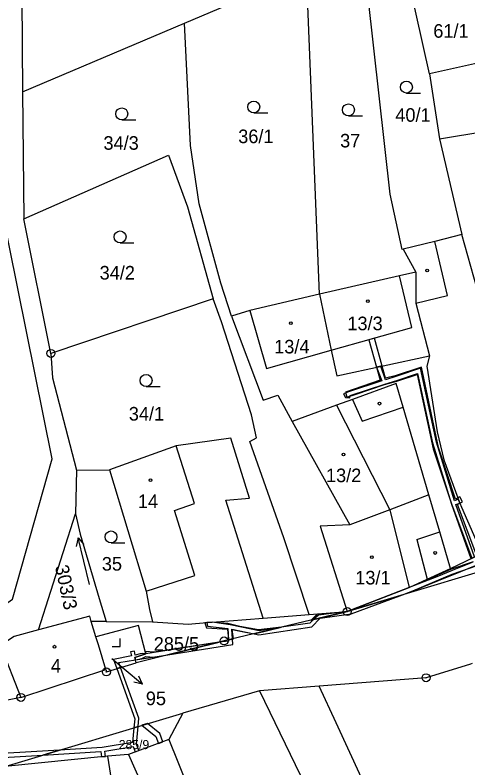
# Model space of a CAD drawing. Extents: x -779723 to -777378, y -1011169 to -1009297.
# Drawn here: x -779128.1 to -779071.4, y -1010301.7 to -1010207.4 of the extents above; entities that cross this region are included whole.
import ezdxf

# ---------------------------------------------------------------- set-up
doc = ezdxf.new("R2010")
doc.units = 0
for name, color, linetype in [('Hranice parcel', 7, 'Continuous'), ('Parcelní čísla', 7, 'Continuous'), ('Pop  PČ popisy', 7, 'Continuous'), ('Vnitřní kresba', 7, 'Continuous'), ('Věcná břemena k části', 7, 'Continuous'), ('Značky bodu BP', 7, 'Continuous'), ('Značky budov', 7, 'Continuous'), ('Značky kultur', 7, 'Continuous')]:
    doc.layers.add(name, color=color, linetype=linetype)

msp = doc.modelspace()

# ---------------------------------------------------------------- linework, layer by layer
at = {"layer": 'Hranice parcel'}
for p, q in [((-779127.44, -1010190.39), (-779127.2, -1010217)), ((-779081.11, -1010229.82), (-779084.45, -1010200.01)), ((-779106.91, -1010208.39), (-779091.64, -1010201.91)), ((-779089.99, -1010242.37), (-779091.64, -1010201.91)), ((-779127.2, -1010217), (-779106.91, -1010208.39)), ((-779106.16, -1010223.74), (-779106.91, -1010208.39)), ((-779127.2, -1010217), (-779127.06, -1010232.92)), ((-779079.62, -1010236.77), (-779081.11, -1010229.82)), ((-779123.64, -1010249.79), (-779127.06, -1010232.92)), ((-779068.8, -1010246.85), (-779072.13, -1010234.9)), ((-779079.48, -1010236.74), (-779079.62, -1010236.77)), ((-779079.48, -1010236.74), (-779077.92, -1010239.59)), ((-779103.32, -1010242.93), (-779123.64, -1010249.79)), ((-779076.18, -1010250.09), (-779076.54, -1010251.4)), ((-779095.21, -1010255.03), (-779093.41, -1010258.3)), ((-779093.41, -1010258.3), (-779086.17, -1010271.27)), ((-779107.93, -1010261.36), (-779116.32, -1010264.37)), ((-779120.42, -1010264.41), (-779120.56, -1010269.87)), ((-779120.42, -1010264.41), (-779116.32, -1010264.37)), ((-779116.32, -1010264.37), (-779111.69, -1010279.58)), ((-779125.19, -1010284.44), (-779120.56, -1010269.87)), ((-779073.55, -1010276.72), (-779069.64, -1010274.85)), ((-779117.61, -1010280.51), (-779116.7, -1010283.39)), ((-779097.04, -1010282.96), (-779091.27, -1010282.5)), ((-779091.27, -1010282.5), (-779086.5, -1010282.14)), ((-779118.01, -1010285.29), (-779118.58, -1010283.38)), ((-779116.7, -1010283.39), (-779118.58, -1010283.38)), ((-779116.7, -1010283.39), (-779110.91, -1010283.41)), ((-779110.91, -1010283.41), (-779106.44, -1010283.7)), ((-779129.95, -1010286.4), (-779127.4, -1010292.89)), ((-779127.4, -1010292.89), (-779116.78, -1010289.39)), ((-779127.4, -1010292.89), (-779137.19, -1010294.93)), ((-779129.38, -1010301.54), (-779107.13, -1010294.85))]:
    msp.add_line(p, q, dxfattribs=at)
for points in [[(-779076.2, -1010214.76), (-779078.76, -1010203.29), (-779079.59, -1010199.58)], [(-779063.08, -1010211.82), (-779064.77, -1010212.2), (-779069.82, -1010213.33), (-779076.2, -1010214.76)], [(-779076.2, -1010214.76), (-779074.94, -1010222.88), (-779072.13, -1010234.9)], [(-779139.88, -1010286.86), (-779135.87, -1010285.81), (-779128.47, -1010280.58), (-779123.49, -1010263.01), (-779132.14, -1010220.3)], [(-779101.02, -1010245.11), (-779102.33, -1010241), (-779105.07, -1010231.05), (-779106.16, -1010223.74)], [(-779127.06, -1010232.92), (-779108.9, -1010224.93), (-779106.53, -1010231.41), (-779103.32, -1010242.93)], [(-779072.13, -1010234.9), (-779075.52, -1010235.75), (-779079.48, -1010236.74)], [(-779077.92, -1010239.59), (-779079.97, -1010240.06), (-779089.99, -1010242.37)], [(-779077.92, -1010239.59), (-779077.92, -1010243.48), (-779076.18, -1010250.09)], [(-779089.99, -1010242.37), (-779098.71, -1010244.39), (-779101.02, -1010245.11)], [(-779089.99, -1010242.37), (-779088.5, -1010249.4), (-779087.83, -1010252.59), (-779076.18, -1010250.09)], [(-779091.27, -1010282.5), (-779094.46, -1010272.88), (-779098.72, -1010260.84), (-779097.87, -1010260.36), (-779098.52, -1010257.5), (-779102.28, -1010245.85), (-779103.32, -1010242.93)], [(-779101.02, -1010245.11), (-779097.05, -1010255.65), (-779095.21, -1010255.03)], [(-779123.64, -1010249.79), (-779123.44, -1010252.85), (-779120.42, -1010264.41)], [(-779037.66, -1010249.73), (-779040.66, -1010261.41), (-779050.79, -1010270.34), (-779061.75, -1010274.71), (-779086.5, -1010282.14)], [(-779076.54, -1010251.4), (-779075.23, -1010259.6), (-779074.39, -1010263.13), (-779072.64, -1010267.9), (-779072.39, -1010268.55), (-779072.2, -1010269.07), (-779069.64, -1010274.85)], [(-779076.26, -1010267.51), (-779079.49, -1010256.51), (-779080.36, -1010253.56), (-779085.85, -1010255.56), (-779087.87, -1010256.29), (-779093.41, -1010258.3)], [(-779097.04, -1010282.96), (-779101.73, -1010268.16), (-779098.76, -1010267.92), (-779101.09, -1010260.41), (-779107.93, -1010261.36)], [(-779076.26, -1010267.51), (-779081.16, -1010269.37), (-779086.17, -1010271.27)], [(-779073.55, -1010276.72), (-779074.9, -1010272.13), (-779076.26, -1010267.51)], [(-779120.56, -1010269.87), (-779119.96, -1010272.44), (-779117.61, -1010280.51)], [(-779086.17, -1010271.27), (-779089.91, -1010271.43), (-779086.5, -1010282.14)], [(-779086.5, -1010282.14), (-779078.75, -1010279.13), (-779076.48, -1010278.07), (-779073.55, -1010276.72)], [(-779111.69, -1010279.58), (-779111.28, -1010281.87), (-779110.91, -1010283.41)], [(-779118.58, -1010283.38), (-779118.78, -1010282.71), (-779125.19, -1010284.44)], [(-779086.5, -1010282.14), (-779101.94, -1010285.82), (-779112.94, -1010288.54)], [(-779106.44, -1010283.7), (-779104.11, -1010283.52), (-779103.42, -1010283.46), (-779097.04, -1010282.96)], [(-779112.94, -1010288.54), (-779113.12, -1010287.88), (-779111.73, -1010287.42), (-779112.67, -1010283.87), (-779118.01, -1010285.29)], [(-779125.19, -1010284.44), (-779128.24, -1010285.26), (-779129.95, -1010286.4)], [(-779116.78, -1010289.39), (-779117.7, -1010286.32), (-779118.01, -1010285.29)], [(-779116.78, -1010289.39), (-779116.69, -1010289.7), (-779112.94, -1010288.54)], [(-779070.83, -1010288.65), (-779071.05, -1010288.72), (-779076.63, -1010290.43), (-779079.33, -1010290.64), (-779090.04, -1010291.48)], [(-779107.24, -1010315.22), (-779102.83, -1010313.22), (-779096.1, -1010312.69), (-779092.74, -1010318.04), (-779088.64, -1010315.52), (-779088.67, -1010313.8), (-779087.34, -1010313.07), (-779081.53, -1010309.87), (-779087.9, -1010296.09), (-779090.04, -1010291.48)], [(-779090.04, -1010291.48), (-779097.5, -1010292.06), (-779107.13, -1010294.85)], [(-779107.13, -1010294.85), (-779108.85, -1010298.16), (-779113.91, -1010300.03)], [(-779113.91, -1010300.03), (-779116.55, -1010300.26), (-779129.38, -1010301.54)], [(-779113.91, -1010300.03), (-779109.3, -1010310.52), (-779107.24, -1010315.22)]]:
    msp.add_lwpolyline(points, dxfattribs=at)
at = {"layer": 'Pop  PČ popisy'}
for p, q in [((-779116, -1010288.01), (-779114.46, -1010289.32)), ((-779114.46, -1010289.32), (-779112.161, -1010291.249)), ((-779112.161, -1010291.249), (-779112.606, -1010290.222)), ((-779112.161, -1010291.249), (-779113.25, -1010290.989))]:
    msp.add_line(p, q, dxfattribs=at)
at = {"layer": 'Vnitřní kresba'}
for p, q in [((-779074.94, -1010222.88), (-779067.91, -1010221.73)), ((-779078.41, -1010246.55), (-779079.97, -1010240.06)), ((-779098.71, -1010244.39), (-779096.62, -1010251.69)), ((-779088.5, -1010249.4), (-779078.41, -1010246.55)), ((-779096.62, -1010251.69), (-779088.5, -1010249.4)), ((-779085.85, -1010255.56), (-779084.65, -1010258.28)), ((-779087.87, -1010256.29), (-779081.16, -1010269.37)), ((-779084.65, -1010258.28), (-779079.49, -1010256.51)), ((-779105.66, -1010268.59), (-779107.93, -1010261.36)), ((-779108.14, -1010269.47), (-779105.66, -1010268.59)), ((-779105.62, -1010277.63), (-779108.14, -1010269.47)), ((-779081.16, -1010269.37), (-779078.75, -1010279.13)), ((-779077.79, -1010273.1), (-779074.9, -1010272.13)), ((-779077.79, -1010273.1), (-779076.48, -1010278.07)), ((-779111.69, -1010279.58), (-779105.62, -1010277.63)), ((-779097.5, -1010292.06), (-779087.34, -1010313.07)), ((-779108.85, -1010298.16), (-779102.83, -1010313.22)), ((-779116.55, -1010300.26), (-779115.17, -1010309.24))]:
    msp.add_line(p, q, dxfattribs=at)
msp.add_lwpolyline([(-779077.92, -1010243.48), (-779073.96, -1010242.51), (-779075.52, -1010235.75)], dxfattribs=at)
at = {"layer": 'Věcná břemena k části'}
for points in [[(-779082.13, -1010251.37), (-779083.1, -1010247.88), (-779083.78, -1010248.07), (-779082.82, -1010251.51)], [(-779086.16, -1010255.06), (-779081.79, -1010253.63), (-779080.27, -1010253.17), (-779077.7, -1010252.31), (-779075.82, -1010261.01), (-779073.45, -1010268.66), (-779071, -1010275.5), (-779070.55, -1010275.28), (-779072.9, -1010268.73), (-779072.39, -1010268.55), (-779072.58, -1010268.05), (-779073.06, -1010268.25), (-779075.34, -1010260.89), (-779077.32, -1010251.65), (-779080.43, -1010252.7), (-779081.71, -1010253.08), (-779082.28, -1010251.4), (-779082.82, -1010251.51), (-779082.19, -1010253.23), (-779086.49, -1010254.64), (-779086.96, -1010254.87), (-779086.74, -1010255.32), (-779086.19, -1010255.37)], [(-779082.82, -1010251.51), (-779082.37, -1010253.12), (-779086.74, -1010254.64), (-779086.54, -1010255.25), (-779085.5, -1010254.95), (-779081.84, -1010253.68), (-779080.28, -1010253.27), (-779077.74, -1010252.42), (-779075.74, -1010261.75), (-779073.46, -1010268.65), (-779070.9, -1010275.45), (-779070.27, -1010275.15), (-779072.69, -1010268.7), (-779072.39, -1010268.55), (-779072.64, -1010267.9), (-779072.92, -1010268.04), (-779075.06, -1010261.57), (-779077.22, -1010251.5), (-779080.48, -1010252.59), (-779081.7, -1010252.91), (-779082.13, -1010251.37)], [(-779072.39, -1010268.55), (-779072.08, -1010268.4), (-779072.39, -1010267.77), (-779072.64, -1010267.9)], [(-779086.02, -1010282.42), (-779079.91, -1010280.16), (-779086.5, -1010282.14), (-779089.9, -1010282.95)], [(-779089.9, -1010282.95), (-779090.72, -1010283.15), (-779091.2, -1010283.58), (-779094.76, -1010284.11), (-779098.19, -1010284.93), (-779097.57, -1010285.05), (-779090.96, -1010284.04)], [(-779086.5, -1010282.14), (-779090.44, -1010282.64), (-779091.02, -1010283.22)], [(-779089.9, -1010282.95), (-779086.5, -1010282.14), (-779090.12, -1010282.6), (-779090.72, -1010283.15)], [(-779101.37, -1010285.68), (-779100.78, -1010285.54), (-779100.91, -1010284.37), (-779100.08, -1010284.57), (-779098.19, -1010284.93), (-779094.76, -1010284.11), (-779097.61, -1010284.43), (-779099.96, -1010283.99), (-779101.49, -1010283.62), (-779103.42, -1010283.46), (-779104.34, -1010283.53), (-779104.16, -1010284.17), (-779101.52, -1010284.32)], [(-779094.76, -1010284.11), (-779097.55, -1010284.55), (-779101.18, -1010283.8), (-779103.42, -1010283.46), (-779104.11, -1010283.52), (-779104.02, -1010283.98), (-779101.46, -1010284.27), (-779101.37, -1010285.68), (-779100.89, -1010285.57), (-779100.95, -1010284.36), (-779098.19, -1010284.93)], [(-779100.85, -1010286.27), (-779100.89, -1010285.57), (-779101.37, -1010285.68), (-779101.37, -1010285.85), (-779102.57, -1010285.98), (-779108.99, -1010287.56)], [(-779108.99, -1010287.56), (-779102.57, -1010285.98), (-779111.73, -1010287.42), (-779113.12, -1010287.88), (-779113.04, -1010288.17)], [(-779108.99, -1010287.56), (-779102.57, -1010285.98), (-779110.75, -1010287.23), (-779111.8, -1010287.14), (-779111.73, -1010287.42), (-779113.12, -1010287.88), (-779113.04, -1010288.17), (-779112.27, -1010288.03), (-779111.74, -1010287.76), (-779110.73, -1010287.83)], [(-779114.92, -1010289.15), (-779115.15, -1010288.53), (-779113.04, -1010288.17), (-779113.12, -1010287.88), (-779111.73, -1010287.42), (-779112.22, -1010287.4), (-779112.47, -1010287.45), (-779113.07, -1010287.58), (-779113.18, -1010287.09), (-779113.66, -1010287.19), (-779113.56, -1010287.69), (-779115.81, -1010288.15), (-779115.37, -1010289.29)], [(-779112.73, -1010296.53), (-779112.63, -1010295.5), (-779114.92, -1010289.15), (-779115.37, -1010289.29), (-779113.13, -1010295.56), (-779113.24, -1010296.69)], [(-779112.25, -1010296.39), (-779110.49, -1010297.77), (-779110.18, -1010298.65), (-779109.62, -1010298.44), (-779109.99, -1010297.41), (-779111.55, -1010296.18)], [(-779112.63, -1010299.56), (-779112.93, -1010298.74), (-779112.73, -1010296.53), (-779113.24, -1010296.69), (-779113.41, -1010298.55), (-779117.21, -1010299.17), (-779122.56, -1010299.49), (-779124.64, -1010300.11), (-779117.39, -1010299.68), (-779117.29, -1010300.33), (-779116.79, -1010300.28), (-779116.9, -1010299.63), (-779113.34, -1010299.05), (-779113.09, -1010299.73)], [(-779124.64, -1010300.11), (-779122.56, -1010299.49), (-779133.3, -1010300.13), (-779147.73, -1010303.19), (-779149.42, -1010303.43), (-779152.32, -1010304.88), (-779155.18, -1010307.73), (-779154.33, -1010307.6), (-779152.02, -1010305.3), (-779149.26, -1010303.91), (-779147.64, -1010303.68), (-779133.24, -1010300.63)]]:
    msp.add_lwpolyline(points, close=True, dxfattribs=at)
for points in [[(-779070.73, -1010275.9), (-779073.57, -1010276.87), (-779077.97, -1010278.77), (-779078.75, -1010279.13), (-779086.5, -1010282.14), (-779079.91, -1010280.16), (-779078.27, -1010279.55), (-779073.35, -1010277.43), (-779070.23, -1010276.37)], [(-779070.83, -1010275.98), (-779073.36, -1010277.01), (-779075.26, -1010277.78), (-779078.75, -1010279.13), (-779086.5, -1010282.14), (-779079.91, -1010280.16), (-779078.26, -1010279.53), (-779075.08, -1010278.24), (-779073.18, -1010277.47), (-779070.42, -1010276.35)]]:
    msp.add_lwpolyline(points, dxfattribs=at)
at = {"layer": 'Značky bodu BP'}
for centre, radius in [((-779123.64, -1010249.79), 0.5), ((-779123.64, -1010249.79), 0.0303), ((-779086.5, -1010282.14), 0.5), ((-779086.5, -1010282.14), 0.0303), ((-779101.94, -1010285.82), 0.5), ((-779101.94, -1010285.82), 0.0303), ((-779116.69, -1010289.7), 0.5), ((-779116.69, -1010289.7), 0.0303), ((-779076.63, -1010290.43), 0.5), ((-779076.63, -1010290.43), 0.0303), ((-779127.4, -1010292.89), 0.5), ((-779127.4, -1010292.89), 0.0303)]:
    msp.add_circle(centre, radius, dxfattribs=at)
at = {"layer": 'Značky budov'}
for centre in [(-779076.487, -1010239.409), (-779083.937, -1010243.239), (-779093.587, -1010245.989), (-779082.457, -1010256.079), (-779086.977, -1010262.449), (-779111.157, -1010265.669), (-779083.417, -1010275.309), (-779075.497, -1010274.789), (-779123.197, -1010286.539)]:
    msp.add_circle(centre, 0.175, dxfattribs=at)
at = {"layer": 'Značky kultur'}
for p, q in [((-779079.093, -1010217.16), (-779077.343, -1010217.16)), ((-779098.223, -1010219.66), (-779096.473, -1010219.66)), ((-779114.763, -1010220.52), (-779113.013, -1010220.52)), ((-779086.353, -1010220.02), (-779084.603, -1010220.02)), ((-779114.983, -1010235.94), (-779113.233, -1010235.94)), ((-779111.723, -1010253.93), (-779109.973, -1010253.93)), ((-779120.242, -1010272.91), (-779120.492, -1010273.98)), ((-779118.79, -1010278.732), (-779120.242, -1010272.91)), ((-779120.242, -1010272.91), (-779119.519, -1010273.737)), ((-779116.113, -1010273.53), (-779114.363, -1010273.53)), ((-779114.97, -1010286.53), (-779114.97, -1010285.53)), ((-779115.971, -1010286.53), (-779114.97, -1010286.53))]:
    msp.add_line(p, q, dxfattribs=at)
for centre in [(-779079.093, -1010216.41), (-779098.223, -1010218.91), (-779086.353, -1010219.27), (-779114.763, -1010219.77), (-779114.983, -1010235.19), (-779111.723, -1010253.18), (-779116.113, -1010272.78)]:
    msp.add_circle(centre, 0.75, dxfattribs=at)

# ---------------------------------------------------------------- texts
at = {"layer": 'Parcelní čísla'}
for s, height, p in [('61/1', 1.7, (-779075.72, -1010210.23)), ('40/1', 1.7, (-779080.48, -1010220.76)), ('36/1', 1.7, (-779100.17, -1010223.44)), ('34/3', 1.7, (-779117.06, -1010224.27)), ('37', 1.7, (-779087.4, -1010223.98)), ('34/2', 1.7, (-779117.54, -1010240.53)), ('13/3', 1.7, (-779086.49, -1010246.88)), ('13/4', 1.7, (-779095.66, -1010249.789)), ('34/1', 1.7, (-779113.88, -1010258.2)), ('13/2', 1.7, (-779089.17, -1010265.919)), ('14', 1.7, (-779112.742, -1010269.16)), ('35', 1.7, (-779117.26, -1010277)), ('13/1', 1.7, (-779085.5, -1010278.74)), ('285/5', 1.7, (-779110.76, -1010287.039)), ('4', 1.7, (-779123.65, -1010289.78)), ('95', 1.7, (-779111.75, -1010293.863)), ('285/9', 1.14, (-779115.139, -1010299.37))]:
    msp.add_text(s, height=height, dxfattribs=at).set_placement(p)
msp.add_text('303/3', height=1.7, rotation=282, dxfattribs=at).set_placement((-779123.141, -1010276.476))

doc.saveas('drawing.dxf')
